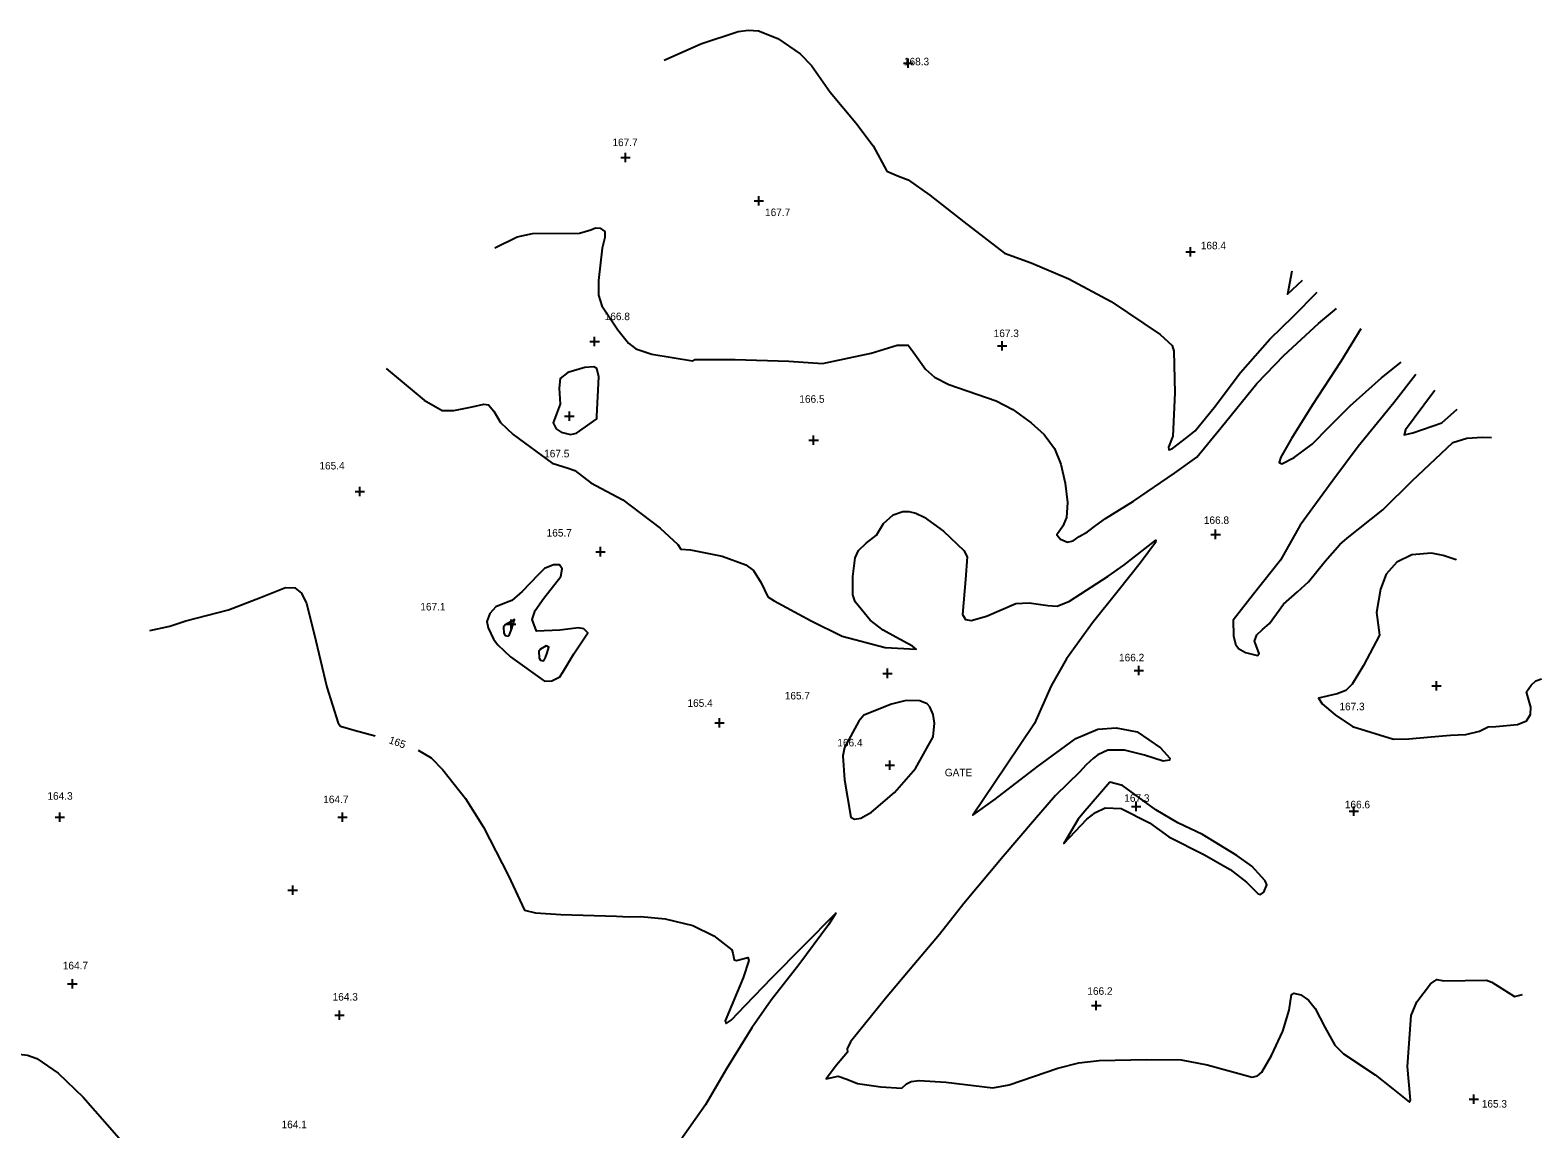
# Model space of a CAD drawing. Extents: x 1475150 to 2003689, y 770235 to 1112803.
# Drawn here: x 2000017.1 to 2000417.2, y 774517.3 to 774808.8 of the extents above; entities that cross this region are included whole.
import ezdxf

# ---------------------------------------------------------------- set-up
doc = ezdxf.new("R2010")
doc.units = 0
for name, color, linetype in [('RD_DTM_Major1', 7, 'Continuous'), ('RD_DTM_Major1_Lbl', 7, 'Continuous'), ('RD_DTM_Minor1', 7, 'Continuous'), ('RD_DTM_Spot_Elev', 7, 'Continuous'), ('RD_TX_Misc1', 7, 'Continuous')]:
    doc.layers.add(name, color=color, linetype=linetype)

msp = doc.modelspace()

# ---------------------------------------------------------------- linework, layer by layer
at = {"layer": 'RD_DTM_Major1'}
for points in [[(2000048.83, 774649.51), (2000054.14, 774650.7), (2000058.38, 774652.08), (2000069.76, 774655.02), (2000078.18, 774658.27), (2000084.88, 774660.89), (2000087.33, 774660.84), (2000089.12, 774659.4), (2000090.41, 774656.71), (2000092.42, 774648.63), (2000095.83, 774634.45), (2000098.81, 774624.91), (2000099.46, 774624.09), (2000103.03, 774623.04), (2000108.67, 774621.52)], [(2000120.07, 774617.78), (2000123.5, 774615.71), (2000126.64, 774612.57), (2000132.58, 774604.94), (2000137.42, 774597.28), (2000144.05, 774584.39), (2000148.3, 774575.26), (2000151.22, 774574.55), (2000157.88, 774574.13), (2000172.64, 774573.66), (2000176.06, 774573.5), (2000179.17, 774573.63), (2000185.59, 774572.96), (2000192.95, 774571.21), (2000198.55, 774568.45), (2000203.3, 774564.72), (2000203.53, 774563.91), (2000203.9, 774562.12), (2000204.53, 774561.97), (2000207.53, 774562.69), (2000207.83, 774561.89), (2000206.26, 774557.29), (2000201.5, 774545.93), (2000201.76, 774545.25), (2000203.07, 774546.11), (2000206.95, 774550.12), (2000213.86, 774557.31), (2000222.29, 774565.83), (2000230.87, 774574.47), (2000228.91, 774571.43), (2000221.1, 774560.82), (2000213.76, 774551.36), (2000208.6, 774544.03), (2000201.88, 774533.19), (2000196.28, 774523.6), (2000188.08, 774511.94)]]:
    msp.add_lwpolyline(points, dxfattribs=at)
at = {"layer": 'RD_DTM_Minor1'}
for points in [[(2000185.32, 774800.91), (2000195.1, 774805.17), (2000205.01, 774808.49), (2000207.73, 774808.83), (2000210.36, 774808.64), (2000215.49, 774806.66), (2000221.42, 774802.54), (2000224.39, 774799.44), (2000229.4, 774792.36), (2000236.22, 774784.25), (2000240.77, 774778.14), (2000244.45, 774771.41), (2000247.5, 774770.05), (2000250.07, 774769.14), (2000255.86, 774765.06), (2000264.89, 774758), (2000275.62, 774749.69), (2000282.71, 774747.07), (2000292.74, 774742.86), (2000303.95, 774736.82), (2000316.93, 774728.04), (2000320.17, 774725.17), (2000320.61, 774723.61), (2000320.83, 774712.6), (2000320.29, 774701.08), (2000319.15, 774698.14), (2000319.24, 774697.45), (2000320.22, 774697.81), (2000323.99, 774700.75), (2000326.24, 774702.46), (2000331.23, 774708.73), (2000338.27, 774717.99), (2000346.02, 774726.83), (2000352.34, 774732.95), (2000358.56, 774739.28)], [(2000140.42, 774751.1), (2000146.35, 774753.97), (2000150.41, 774754.91), (2000162.87, 774754.95), (2000165.9, 774755.87), (2000167.13, 774756.36), (2000168.36, 774756.24), (2000169.59, 774755.38), (2000169.59, 774753.78), (2000168.85, 774750.95), (2000167.89, 774742.41), (2000167.9, 774738.47), (2000168.75, 774735.67), (2000173.07, 774729.27), (2000175.91, 774725.74), (2000177.8, 774724.22), (2000182.02, 774722.8), (2000192.82, 774721.08), (2000193.44, 774721.43), (2000204.19, 774721.42), (2000218.39, 774721.03), (2000227.32, 774720.38), (2000240.25, 774723.11), (2000247.18, 774725.2), (2000250.08, 774725.25), (2000251.36, 774723.45), (2000254.69, 774718.82), (2000257.08, 774716.71), (2000260.83, 774714.79), (2000273.39, 774710.49), (2000277.86, 774708.2), (2000282.73, 774704.66), (2000286.16, 774701.5), (2000288.87, 774697.85), (2000290.62, 774693.65), (2000291.78, 774688.65), (2000292.37, 774683.46), (2000292.08, 774679.49), (2000291.08, 774677.19), (2000289.53, 774674.9), (2000290.54, 774673.72), (2000292.37, 774672.92), (2000293.87, 774673.34), (2000295.47, 774674.46), (2000297.67, 774675.7), (2000299.86, 774677.37), (2000302.41, 774679.23), (2000309.89, 774683.8), (2000320.73, 774691.25), (2000326.64, 774695.52), (2000333.13, 774703.39), (2000342.56, 774715.02), (2000349.86, 774722.56), (2000358.98, 774730.97), (2000363.77, 774734.94)], [(2000351.88, 774744.85), (2000350.71, 774738.77), (2000354.69, 774742.51)], [(2000370.22, 774729.56), (2000364.87, 774720.87), (2000357.37, 774709.39), (2000351.78, 774700.5), (2000348.95, 774695.55), (2000348.54, 774694.08), (2000349.2, 774693.74), (2000352.51, 774695.38), (2000357.29, 774698.94), (2000361.76, 774703.55), (2000367.39, 774709.16), (2000375.68, 774716.6), (2000380.85, 774720.69)], [(2000111.53, 774719.06), (2000121.69, 774710.63), (2000126.46, 774707.9), (2000129.56, 774707.89), (2000134.38, 774708.88), (2000137.51, 774709.58), (2000138.68, 774709.44), (2000140.14, 774707.68), (2000141.9, 774704.71), (2000145.25, 774701.52), (2000155.64, 774693.89), (2000159.89, 774692.63), (2000161.59, 774691.95), (2000165.85, 774688.67), (2000172.83, 774685.02), (2000174.35, 774684.17), (2000184.24, 774676.7), (2000188.93, 774672.33), (2000189.77, 774671.06), (2000192.29, 774670.88), (2000200.72, 774669.25), (2000207.02, 774666.93), (2000209.04, 774665.4), (2000211.08, 774662.17), (2000212.81, 774658.48), (2000214.48, 774657.37), (2000224.34, 774652.05), (2000232.57, 774648.01), (2000243.98, 774645.02), (2000252.17, 774644.52), (2000251.22, 774645.35), (2000246.79, 774647.72), (2000243.47, 774649.57), (2000239.96, 774652.23), (2000237.62, 774655.13), (2000235.97, 774657.1), (2000235.39, 774658.97), (2000235.35, 774663.88), (2000236.04, 774668.81), (2000236.88, 774670.73), (2000238.97, 774672.66), (2000241.65, 774674.79), (2000243.56, 774677.91), (2000246.09, 774680.19), (2000248.63, 774681.09), (2000250.23, 774681.11), (2000252.12, 774680.67), (2000254.32, 774679.63), (2000259.42, 774675.86), (2000264.89, 774670.7), (2000265.71, 774669.09), (2000265.32, 774663.08), (2000264.53, 774653.74), (2000265.28, 774652.47), (2000266.78, 774652.15), (2000270.84, 774653.3), (2000278.66, 774656.67), (2000282.2, 774656.83), (2000287.18, 774656.16), (2000289.61, 774655.93), (2000292.9, 774657.31), (2000303.12, 774663.89), (2000307.34, 774666.85), (2000315.79, 774673.49), (2000315.7, 774672.89), (2000311.68, 774667.37), (2000305.76, 774660.03), (2000299.01, 774651.55), (2000292.05, 774642), (2000288.04, 774634.86), (2000283.57, 774624.82), (2000275.96, 774613.54), (2000267.27, 774600.47), (2000273.12, 774604.74), (2000284.29, 774613.32), (2000294.53, 774620.83), (2000300.38, 774623.29), (2000305.27, 774623.69), (2000310.82, 774622.63), (2000317.04, 774618.4), (2000319.55, 774615.62), (2000319.42, 774615.09), (2000317.7, 774614.83), (2000312.81, 774616.42), (2000307.52, 774617.74), (2000304.21, 774617.74), (2000303.02, 774617.74), (2000300.38, 774616.55), (2000299.23, 774615.62), (2000297.35, 774613.82), (2000295.56, 774611.88), (2000289.17, 774605.75), (2000283.58, 774599.22), (2000275.25, 774589.51), (2000264.88, 774577.1), (2000258.41, 774568.8), (2000251.58, 774560.79), (2000244.09, 774551.83), (2000234.81, 774540.36), (2000233.86, 774538.48), (2000233.99, 774537.57), (2000231.04, 774534.12), (2000228.31, 774530.49), (2000229.43, 774530.78), (2000231.53, 774531.2), (2000233.76, 774530.48), (2000236.66, 774529.3), (2000242.8, 774528.36), (2000248.41, 774528.02), (2000249.59, 774529.2), (2000250.85, 774529.79), (2000252.99, 774530.11), (2000260.09, 774529.63), (2000272.57, 774528.15), (2000276.9, 774528.92), (2000289.76, 774533.36), (2000295.39, 774534.78), (2000300.79, 774535.39), (2000313.44, 774535.68), (2000322.5, 774535.59), (2000329.42, 774534.21), (2000341.35, 774531.01), (2000342.77, 774531.32), (2000343.91, 774532.34), (2000346.51, 774536.76), (2000349.5, 774543.16), (2000351.18, 774548.72), (2000351.83, 774552.91), (2000352.43, 774553.29), (2000354.28, 774552.86), (2000356.31, 774551.42), (2000358.11, 774549.2), (2000360.63, 774544.23), (2000363.25, 774539.42), (2000365.59, 774537.12), (2000374.03, 774531.59), (2000378.72, 774527.84), (2000383.1, 774524.3), (2000383.38, 774524.9), (2000382.56, 774533.8), (2000383.59, 774547.33), (2000385.08, 774551), (2000388.69, 774555.7), (2000390.36, 774556.89), (2000392.19, 774556.52), (2000403.56, 774556.74), (2000404.94, 774556.22), (2000410.95, 774552.42), (2000413.05, 774552.9)], [(2000160.44, 774701.52), (2000162.08, 774701.86), (2000167.48, 774705.69), (2000167.44, 774706.36), (2000168.03, 774716.8), (2000167.47, 774719.07), (2000166.69, 774719.5), (2000164.27, 774719.28), (2000159.76, 774717.96), (2000157.7, 774716.38), (2000157.43, 774713.83), (2000157.72, 774709.55), (2000155.9, 774704.62), (2000156.68, 774703.06), (2000157.98, 774702.16), (2000160.44, 774701.52)], [(2000384.78, 774717.41), (2000378.91, 774709.95), (2000369.51, 774698.31), (2000362.77, 774689.29), (2000354.05, 774677.42), (2000348.84, 774668.14), (2000341.73, 774659.17), (2000336.28, 774652.25), (2000336.36, 774648.11), (2000336.89, 774645.84), (2000337.73, 774644.73), (2000339.59, 774643.65), (2000342.75, 774642.85), (2000343.18, 774643.37), (2000342.01, 774646.65), (2000342.62, 774648.35), (2000344.13, 774649.75), (2000345.93, 774651.35), (2000349.7, 774656.53), (2000353.38, 774659.78), (2000356.28, 774662.39), (2000360.77, 774667.95), (2000364.59, 774672.36), (2000366.59, 774674.01), (2000376.03, 774681.49), (2000383.84, 774689.22), (2000394.62, 774699.38), (2000398.3, 774700.53), (2000402.49, 774700.84), (2000404.82, 774700.7)], [(2000389.85, 774713.18), (2000389.19, 774712.44), (2000382.03, 774702.74), (2000381.7, 774701.42), (2000384.02, 774702.01), (2000391.64, 774704.58), (2000395.78, 774708.24)], [(2000395.6, 774668.15), (2000395.45, 774668.23), (2000392.02, 774669.44), (2000388.93, 774670), (2000383.71, 774669.58), (2000379.7, 774667.65), (2000376.94, 774664.49), (2000375.39, 774660.5), (2000374.37, 774654.28), (2000375.15, 774648.23), (2000370.89, 774640.23), (2000367.9, 774635.3), (2000366.17, 774633.6), (2000363.92, 774632.72), (2000359, 774631.51), (2000359.89, 774630.09), (2000363.41, 774627.09), (2000367.97, 774624.05), (2000378.82, 774620.66), (2000382.89, 774620.75), (2000391.83, 774621.58), (2000394, 774621.77), (2000398.02, 774621.87), (2000401.64, 774622.77), (2000403.95, 774623.93), (2000406.01, 774624.01), (2000411.75, 774624.53), (2000414.15, 774625.53), (2000415.19, 774627.2), (2000415.31, 774629.16), (2000414.41, 774632.23), (2000414.12, 774633.27), (2000415.38, 774635.04), (2000416.62, 774636.11), (2000418.1, 774636.71)], [(2000144.88, 774657.45), (2000143.5, 774656.95), (2000140.64, 774655.78), (2000139.07, 774654.04), (2000138.29, 774651.91), (2000138.61, 774650.18), (2000140.05, 774647.18), (2000141.16, 774645.7), (2000144.52, 774642.55), (2000153.56, 774636.03), (2000155.53, 774636.12), (2000157.65, 774637.22), (2000158.48, 774638.41), (2000161.4, 774643.3), (2000165.09, 774648.92), (2000164.01, 774649.96), (2000162.58, 774650.26), (2000157.63, 774649.63), (2000151.46, 774649.35), (2000150.3, 774652.41), (2000151.08, 774654.85), (2000153.42, 774658.1), (2000157.9, 774663.83), (2000158.28, 774665.87), (2000157.53, 774666.93), (2000155.93, 774666.94), (2000153.61, 774665.96), (2000151.91, 774664.26), (2000147.65, 774659.84), (2000144.88, 774657.45)], [(2000144.7, 774651.94), (2000143.16, 774651.05), (2000142.74, 774650.42), (2000142.79, 774648.78), (2000143.11, 774648.14), (2000143.96, 774647.98), (2000144.17, 774648.14), (2000144.48, 774648.85), (2000144.95, 774650.07), (2000145.59, 774652.45), (2000144.7, 774651.94)], [(2000154.03, 774645.42), (2000152.48, 774644.53), (2000152.07, 774643.9), (2000152.12, 774642.26), (2000152.44, 774641.63), (2000153.28, 774641.47), (2000153.5, 774641.63), (2000153.8, 774642.33), (2000154.28, 774643.55), (2000154.77, 774645.12), (2000154.03, 774645.42)], [(2000255.13, 774630.05), (2000253.2, 774630.88), (2000249.58, 774630.95), (2000245.66, 774629.92), (2000238.27, 774627.07), (2000237.02, 774625.49), (2000233.21, 774618.43), (2000232.73, 774616.21), (2000233.2, 774609.84), (2000234.85, 774599.97), (2000235.82, 774599.46), (2000237.52, 774599.68), (2000240.33, 774601.26), (2000246.45, 774606.55), (2000252, 774612.87), (2000256.72, 774621.33), (2000257.08, 774624.92), (2000256.68, 774627.19), (2000255.83, 774629.23), (2000255.13, 774630.05)], [(2000297.5, 774599.46), (2000299.77, 774601.25), (2000302.39, 774602.43), (2000306.57, 774602.26), (2000314.15, 774598.49), (2000319.28, 774594.76), (2000328.52, 774590.1), (2000335.56, 774586.11), (2000339.85, 774582.72), (2000342.93, 774579.64), (2000343.6, 774579.44), (2000344.41, 774580.06), (2000345.28, 774581.99), (2000344.84, 774583.06), (2000341.24, 774586.93), (2000337.27, 774589.84), (2000328.14, 774595.39), (2000321.67, 774598.43), (2000315.78, 774601.96), (2000306.94, 774608.39), (2000303.62, 774609.29), (2000296.4, 774600.98), (2000295.19, 774599.46), (2000291.42, 774592.95), (2000297.5, 774599.46)], [(2000000.61, 774526.2), (2000003.63, 774528.54), (2000006.45, 774531.8), (2000008.4, 774534.33), (2000010.77, 774536.15), (2000012.36, 774536.8), (2000014.22, 774537.08), (2000016.38, 774536.81), (2000018.83, 774535.89), (2000024.54, 774532.02), (2000031.13, 774525.64), (2000040.72, 774514.81), (2000047.92, 774506.63), (2000049.71, 774502.84), (2000050.61, 774501.03), (2000051.28, 774500.65), (2000050.71, 774500.04), (2000051.4, 774498.02), (2000052.4, 774494.26), (2000051.95, 774492.17), (2000048.39, 774486.6), (2000047.1, 774484.5), (2000046.11, 774482.25), (2000045.63, 774481.59)]]:
    msp.add_lwpolyline(points, dxfattribs=at)
at = {"layer": 'RD_DTM_Spot_Elev'}
for p, q in [((2000248.8, 774800.04), (2000251.3, 774800.04)), ((2000250.05, 774798.79), (2000250.05, 774801.29)), ((2000175.05, 774773.79), (2000175.05, 774776.29)), ((2000173.8, 774775.04), (2000176.3, 774775.04)), ((2000210.48, 774762.26), (2000210.48, 774764.76)), ((2000209.23, 774763.51), (2000211.73, 774763.51)), ((2000323.75, 774750), (2000326.25, 774750)), ((2000325, 774748.75), (2000325, 774751.25)), ((2000165.63, 774726.23), (2000168.13, 774726.23)), ((2000166.88, 774724.98), (2000166.88, 774727.48)), ((2000273.8, 774725.04), (2000276.3, 774725.04)), ((2000275.05, 774723.79), (2000275.05, 774726.29)), ((2000158.92, 774706.4), (2000161.42, 774706.4)), ((2000160.17, 774705.15), (2000160.17, 774707.65)), ((2000223.75, 774700), (2000226.25, 774700)), ((2000225, 774698.75), (2000225, 774701.25)), ((2000103.3, 774686.39), (2000105.8, 774686.39)), ((2000104.55, 774685.14), (2000104.55, 774687.64)), ((2000331.66, 774673.77), (2000331.66, 774676.27)), ((2000330.41, 774675.02), (2000332.91, 774675.02)), ((2000167.2, 774670.42), (2000169.7, 774670.42)), ((2000168.45, 774669.17), (2000168.45, 774671.67)), ((2000144.74, 774649.93), (2000144.74, 774652.43)), ((2000143.49, 774651.18), (2000145.99, 774651.18)), ((2000311.31, 774637.67), (2000311.31, 774640.17)), ((2000243.36, 774638.13), (2000245.86, 774638.13)), ((2000244.61, 774636.88), (2000244.61, 774639.38)), ((2000310.06, 774638.92), (2000312.56, 774638.92)), ((2000390.27, 774633.57), (2000390.27, 774636.07)), ((2000389.02, 774634.82), (2000391.52, 774634.82)), ((2000198.75, 774625), (2000201.25, 774625)), ((2000200, 774623.75), (2000200, 774626.25)), ((2000243.97, 774613.8), (2000246.47, 774613.8)), ((2000245.22, 774612.55), (2000245.22, 774615.05)), ((2000310.58, 774601.59), (2000310.58, 774604.09)), ((2000023.75, 774600), (2000026.25, 774600)), ((2000025, 774598.75), (2000025, 774601.25)), ((2000098.75, 774600), (2000101.25, 774600)), ((2000100, 774598.75), (2000100, 774601.25)), ((2000309.33, 774602.84), (2000311.83, 774602.84)), ((2000367.11, 774601.58), (2000369.61, 774601.58)), ((2000368.36, 774600.33), (2000368.36, 774602.83)), ((2000085.51, 774580.61), (2000088.01, 774580.61)), ((2000086.76, 774579.36), (2000086.76, 774581.86)), ((2000028.3, 774554.49), (2000028.3, 774556.99)), ((2000027.05, 774555.74), (2000029.55, 774555.74)), ((2000099.2, 774546.15), (2000099.2, 774548.65)), ((2000298.75, 774550), (2000301.25, 774550)), ((2000300, 774548.75), (2000300, 774551.25)), ((2000097.95, 774547.4), (2000100.45, 774547.4)), ((2000398.9, 774525.13), (2000401.4, 774525.13)), ((2000400.15, 774523.88), (2000400.15, 774526.38))]:
    msp.add_line(p, q, dxfattribs=at)

# ---------------------------------------------------------------- texts
at = {"layer": 'RD_DTM_Major1_Lbl'}
msp.add_text('165', height=2, rotation=340.6048, dxfattribs=at).set_placement((2000112.11, 774619.64))
at = {"layer": 'RD_DTM_Spot_Elev'}
for s, p in [('168.3', (2000248.95, 774799.5)), ('167.7', (2000171.6, 774778.05)), ('167.7', (2000212.1, 774759.49)), ('168.4', (2000327.72, 774750.67)), ('166.8', (2000169.55, 774731.87)), ('167.3', (2000272.77, 774727.38)), ('166.5', (2000221.2, 774709.95)), ('167.5', (2000153.48, 774695.46)), ('165.4', (2000093.85, 774692.24)), ('166.8', (2000328.53, 774677.78)), ('165.7', (2000154.14, 774674.44)), ('167.1', (2000120.63, 774654.82)), ('166.2', (2000306.03, 774641.33)), ('165.7', (2000217.33, 774631.21)), ('165.4', (2000191.52, 774629.25)), ('167.3', (2000364.51, 774628.34)), ('166.4', (2000231.29, 774618.75)), ('164.3', (2000021.68, 774604.6)), ('164.7', (2000094.87, 774603.69)), ('167.3', (2000307.42, 774604.04)), ('166.6', (2000365.94, 774602.32)), ('164.7', (2000025.76, 774559.59)), ('164.3', (2000097.36, 774551.29)), ('166.2', (2000297.62, 774552.82)), ('165.3', (2000402.28, 774522.9)), ('164.1', (2000083.82, 774517.42))]:
    msp.add_text(s, height=2, dxfattribs=at).set_placement(p)
at = {"layer": 'RD_TX_Misc1'}
msp.add_text('GATE', height=2, dxfattribs=at).set_placement((2000259.8, 774610.82))

doc.saveas('drawing.dxf')
